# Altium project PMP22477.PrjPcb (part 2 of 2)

## Sheet PMP22477_RevC_SH3.SchDoc: Power Limit Circuit
size 431 x 279 mm; Date: Not shown in title block; ApprovedBy: Not shown in title block; CheckedBy: Not shown in title block; Author: Not shown in title block; CompanyName: Not shown in title block; DrawnBy: D Strasser; Engineer: Not shown in title block; Organization: Not shown in title block; Address1: Not shown in title block; Address2: Not shown in title block; Address3: Not shown in title block; Address4: Not shown in title block; DocumentNumber: 3; Revision: Use project parameter SCH_Rev; SheetNumber: 3; SheetTotal: 3; PageSetup: Record=PageOptions¦CenterHorizontal=True¦CenterVertical=True¦PrintScale=1.00¦XCorrection=1.00¦YCorrection=1.00¦PrintKind=0¦BorderSize=5000000¦LeftOffset=0¦BottomOffset=0¦Orientation=2¦PaperLength=1000¦PaperWidth=1000¦Scale=100¦PaperSource=15¦PrintQuality=600¦MediaType=1¦DitherType=10¦PaperKind=Letter¦PrintScaleMode=1
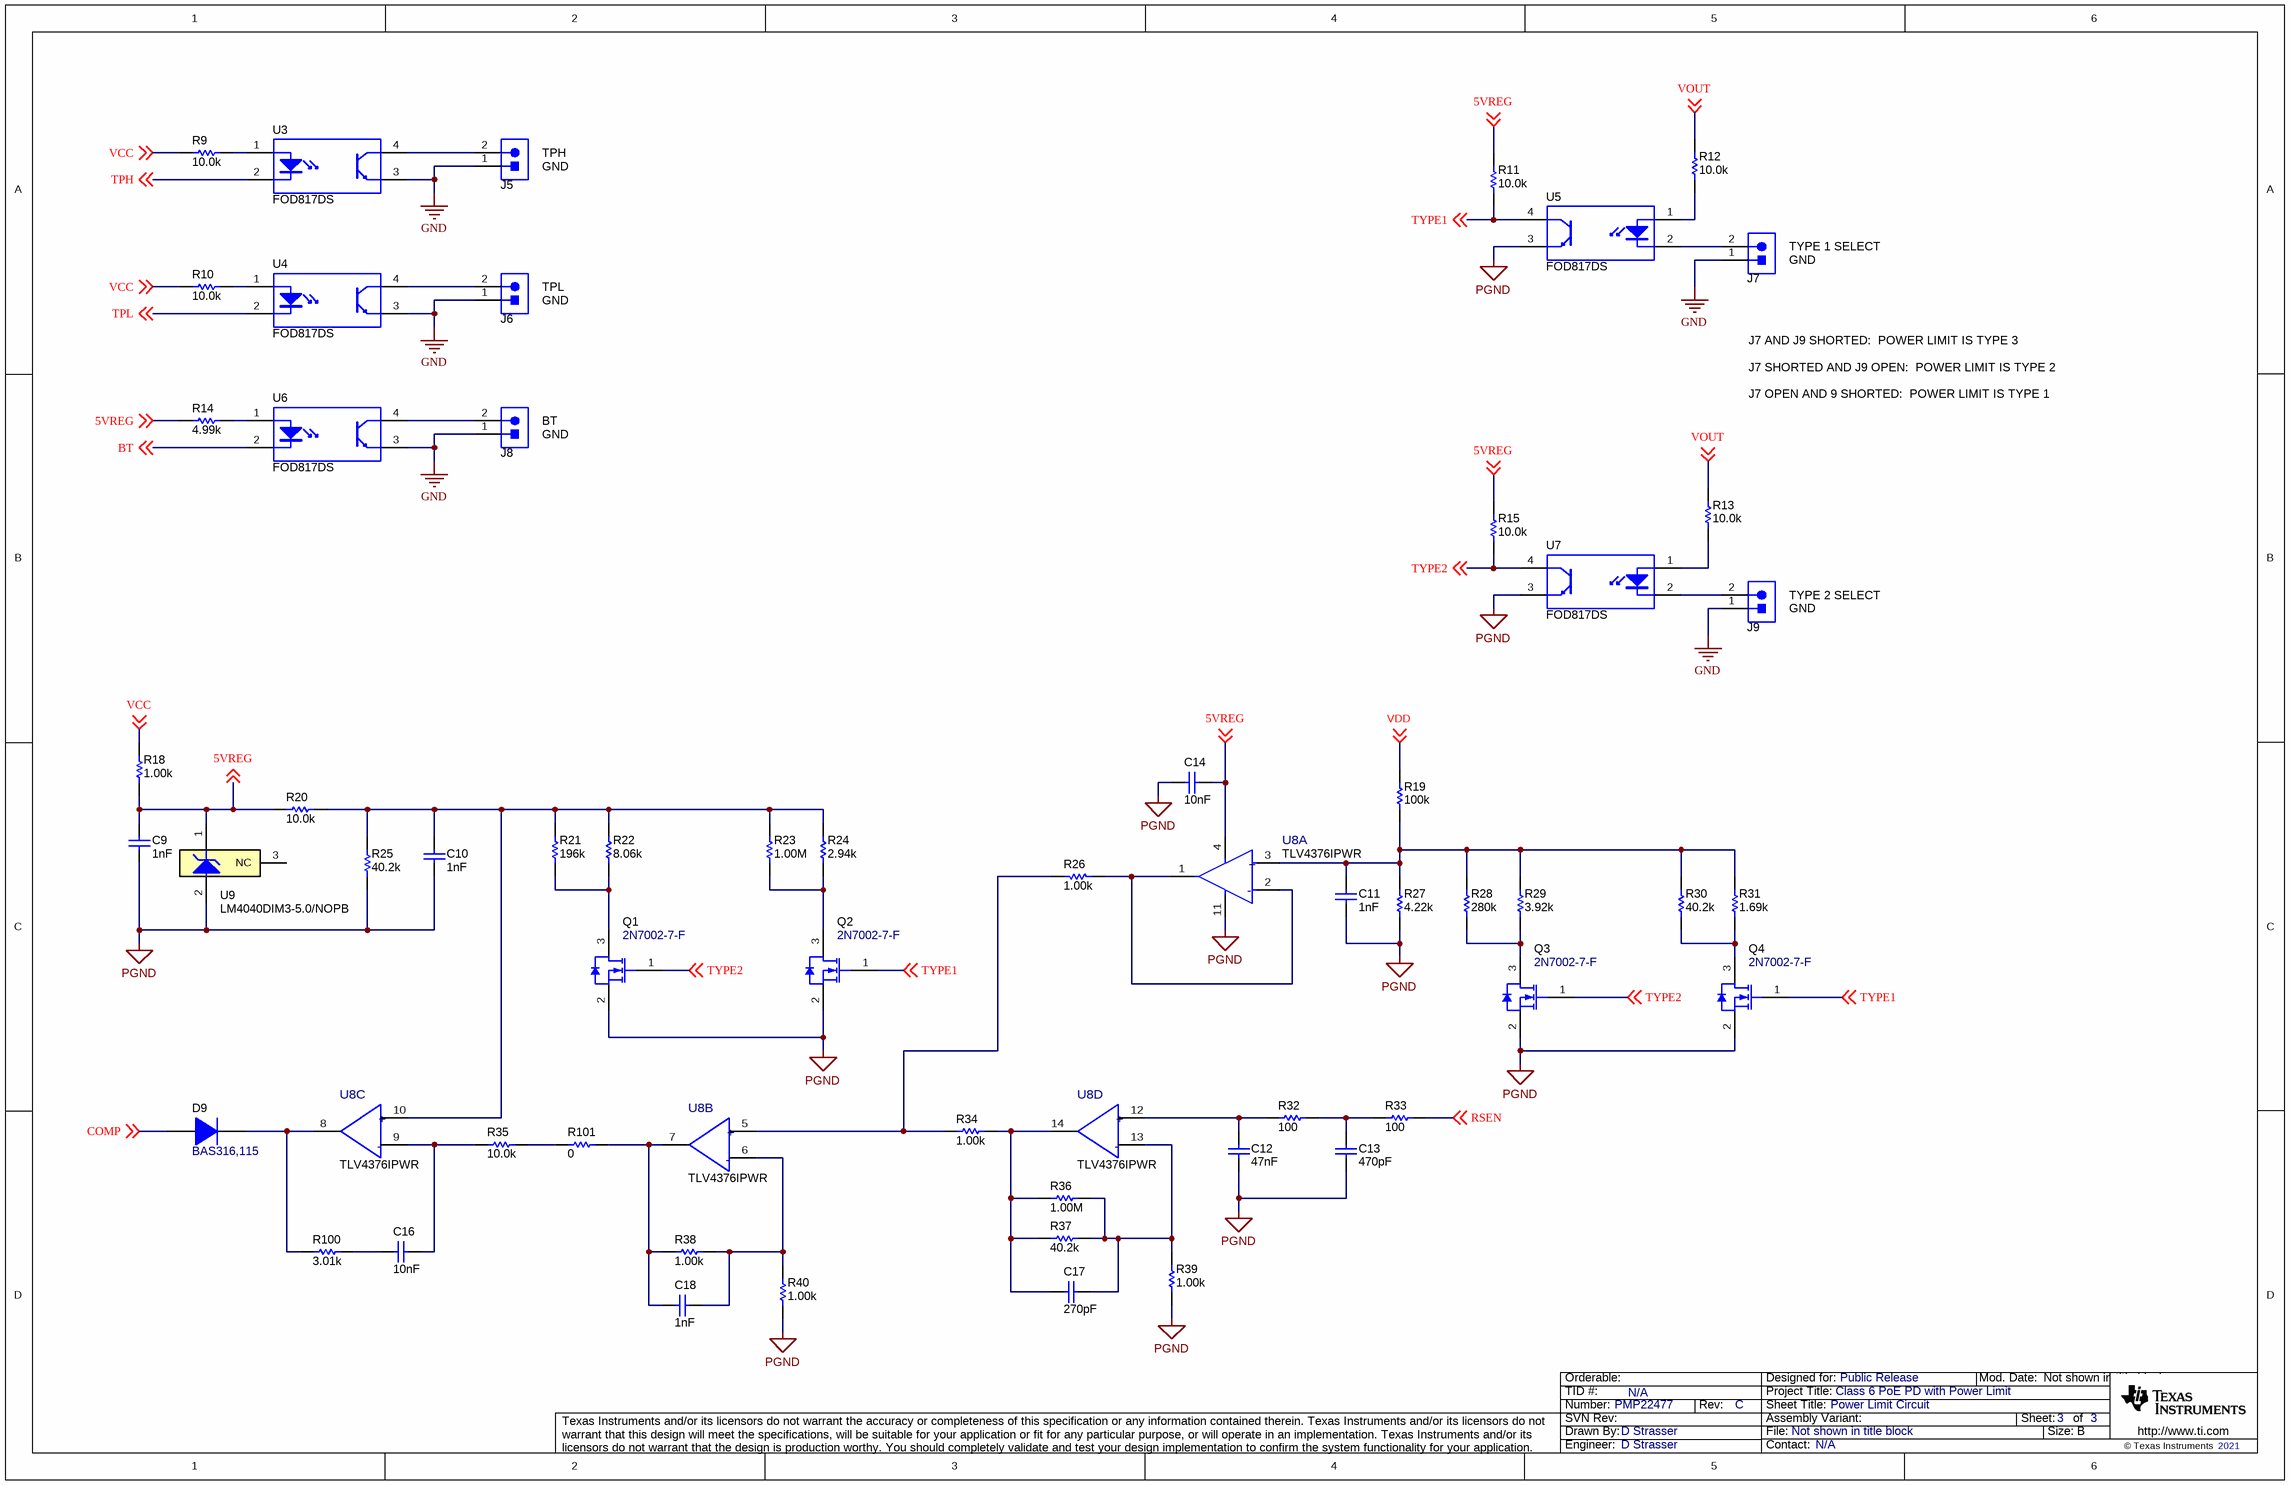
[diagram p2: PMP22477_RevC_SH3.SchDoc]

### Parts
C9  Cap_F: 1nF  [0603L]  (hidden comment: 885012206083)
C10  Cap_F: 1nF  [0603L]  (hidden comment: 885012206083)
C11  Cap_F: 1nF  [0603L]  (hidden comment: 885012206083)
C12  Cap_F: 47nF  [0603L]  (hidden comment: GRM188R71C473KA01D)
C13  ValueDisplayed: 470pF  [0603L]  (hidden comment: GRM1885C1H471JA01D)
C14  Cap_F: 10nF  [0603L]  (hidden comment: GRM188R71H103KA01D)
C16  Cap_F: 10nF  [0603L]  (hidden comment: GRM188R71H103KA01D)
C17  ValueDisplayed: 270pF  [0603L]  (hidden comment: GRM1885C1H271JA01D)
C18  Cap_F: 1nF  [0603L]  (hidden comment: 885012206083)
D9  BAS316,115  [SOD-323]
J5  TSW-102-07-G-S  [TSW-102-07-G-S]  (value not drawn)
J6  TSW-102-07-G-S  [TSW-102-07-G-S]  (value not drawn)
J7  TSW-102-07-G-S  [TSW-102-07-G-S]  (value not drawn)
J8  TSW-102-07-G-S  [TSW-102-07-G-S]  (value not drawn)
J9  TSW-102-07-G-S  [TSW-102-07-G-S]  (value not drawn)
Q1  2N7002-7-F  [SOT-23L]
Q2  2N7002-7-F  [SOT-23L]
Q3  2N7002-7-F  [SOT-23L]
Q4  2N7002-7-F  [SOT-23L]
R9  ValueDisplayed: 10.0k  [0603L]  (hidden comment: CRCW060310K0FKEA)
R10  ValueDisplayed: 10.0k  [0603L]  (hidden comment: CRCW060310K0FKEA)
R11  ValueDisplayed: 10.0k  [0603L]  (hidden comment: CRCW060310K0FKEA)
R12  ValueDisplayed: 10.0k  [0603L]  (hidden comment: CRCW060310K0FKEA)
R13  ValueDisplayed: 10.0k  [0603L]  (hidden comment: CRCW060310K0FKEA)
R14  ValueDisplayed: 4.99k  [0603L]  (hidden comment: CRCW06034K99FKEA)
R15  ValueDisplayed: 10.0k  [0603L]  (hidden comment: CRCW060310K0FKEA)
R18  ValueDisplayed: 1.00k  [0603L]  (hidden comment: CRCW06031K00FKEA)
R19  ValueDisplayed: 100k  [0603L]  (hidden comment: CRCW0603100KFKEA)
R20  ValueDisplayed: 10.0k  [0603L]  (hidden comment: CRCW060310K0FKEA)
R21  ValueDisplayed: 196k  [0603L]  (hidden comment: CRCW0603196KFKEA)
R22  ValueDisplayed: 8.06k  [0603L]  (hidden comment: CRCW06038K06FKEA)
R23  ValueDisplayed: 1.00M  [0603L]  (hidden comment: CRCW06031M00FKEA)
R24  ValueDisplayed: 2.94k  [0603L]  (hidden comment: CRCW06032K94FKEA)
R25  ValueDisplayed: 40.2k  [0603L]  (hidden comment: CRCW060340K2FKEA)
R26  ValueDisplayed: 1.00k  [0603L]  (hidden comment: CRCW06031K00FKEA)
R27  ValueDisplayed: 4.22k  [0603L]  (hidden comment: CRCW06034K22FKEA)
R28  ValueDisplayed: 280k  [0603L]  (hidden comment: CRCW0603280KFKEA)
R29  ValueDisplayed: 3.92k  [0603L]  (hidden comment: CRCW06033K92FKEA)
R30  ValueDisplayed: 40.2k  [0603L]  (hidden comment: CRCW060340K2FKEA)
R31  ValueDisplayed: 1.69k  [0603L]  (hidden comment: CRCW06031K69FKEA)
R32  ValueDisplayed: 100  [0603L]  (hidden comment: CRCW0603100RFKEA)
R33  ValueDisplayed: 100  [0603L]  (hidden comment: CRCW0603100RFKEA)
R34  ValueDisplayed: 1.00k  [0603L]  (hidden comment: CRCW06031K00FKEA)
R35  ValueDisplayed: 10.0k  [0603L]  (hidden comment: CRCW060310K0FKEA)
R36  ValueDisplayed: 1.00M  [0603L]  (hidden comment: CRCW06031M00FKEA)
R37  ValueDisplayed: 40.2k  [0603L]  (hidden comment: CRCW060340K2FKEA)
R38  ValueDisplayed: 1.00k  [0603L]  (hidden comment: CRCW06031K00FKEA)
R39  ValueDisplayed: 1.00k  [0603L]  (hidden comment: CRCW06031K00FKEA)
R40  ValueDisplayed: 1.00k  [0603L]  (hidden comment: CRCW06031K00FKEA)
R100  ValueDisplayed: 3.01k  [0603L]  (hidden comment: CRCW06033K01FKEA)
R101  ValueDisplayed: 0  [0603L]  (hidden comment: ERJ-3GEY0R00V)
U3  FOD817DS  [N04C]
U4  FOD817DS  [N04C]
U5  FOD817DS  [N04C]
U6  FOD817DS  [N04C]
U7  FOD817DS  [N04C]
U8  TLV4376IPWR  [PW0014A-MFG]  (parts A,B,C,D of 4)
U9  LM4040DIM3-5.0/NOPB  [DBZ0003A_L]

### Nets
GND: J5.1 J6.1 J7.1 J8.1 J9.1 U3.3(E) U4.3(E) U6.3(E)
PGND: C9.1 C10.1 C11.1 C12.1 C13.1 C14.1 Q1.2(S) Q2.2(S) Q3.2(S) Q4.2(S) R25.2 R27.1 R39.2 R40.1 U5.3(E) U7.3(E) U8.11(V-) U9.2(A)
5VREG: C9.2 C14.2 R11.1 R14.1 R15.1 R18.1 R20.2 U8.4(V+) U9.1(K) ; off-sheet 5VREG
BT: U6.2(K) ; off-sheet BT
COMP: D9.2(A) ; off-sheet COMP
RSEN: R33.2 ; off-sheet RSEN
TPH: U3.2(K) ; off-sheet TPH
TPL: U4.2(K) ; off-sheet TPL
TYPE1: Q2.1(G) Q4.1(G) R11.2 U5.4(C) ; off-sheet TYPE1
TYPE2: Q1.1(G) Q3.1(G) R15.2 U7.4(C) ; off-sheet TYPE2
VCC: R9.2 R10.2 R18.2 ; off-sheet VCC
VDD: R19.2 ; off-sheet VDD
VOUT: R12.1 R13.1 ; off-sheet VOUT
NetC10_2: C10.2 R20.1 R21.1 R22.1 R23.2 R24.1 R25.1 U8.10(+IN_C)
NetC11_2: C11.2 R19.1 R27.2 R28.1 R29.1 R30.1 R31.1 U8.3(+IN_A)
NetC12_2: C12.2 R32.1 U8.12(+IN_D)
NetC13_2: C13.2 R32.2 R33.1
NetC16_1: C16.1 R100.2
NetC16_2: C16.2 R35.1 U8.9(-IN_C)
NetC17_1: C17.1 R36.1 R37.2 R39.1 U8.13(-IN_D)
NetC17_2: C17.2 R34.2 R36.2 R37.1 U8.14(OUT_D)
NetC18_1: C18.1 R38.2 R40.2 U8.6(-IN_B)
NetC18_2: C18.2 R38.1 R101.1 U8.7(OUT_B)
NetD9_1: D9.1(K) R100.1 U8.8(OUT_C)
NetJ5_2: J5.2 U3.4(C)
NetJ6_2: J6.2 U4.4(C)
NetJ7_2: J7.2 U5.2(K)
NetJ8_2: J8.2 U6.4(C)
NetJ9_2: J9.2 U7.2(K)
NetQ1_3: Q1.3(D) R21.2 R22.2
NetQ2_3: Q2.3(D) R23.1 R24.2
NetQ3_3: Q3.3(D) R28.2 R29.2
NetQ4_3: Q4.3(D) R30.2 R31.2
NetR9_1: R9.1 U3.1(A)
NetR10_1: R10.1 U4.1(A)
NetR12_2: R12.2 U5.1(A)
NetR13_2: R13.2 U7.1(A)
NetR14_2: R14.2 U6.1(A)
NetR26_1: R26.1 U8.1(OUT_A) U8.2(-IN_A)
NetR26_2: R26.2 R34.1 U8.5(+IN_B)
NetR35_2: R35.2 R101.2

Not connected (* = marked no-connect by the designer): U9 3(NC)

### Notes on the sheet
- (near J5) GND
- (near J5) TPH
- (near J6) GND
- (near J6) TPL
- (near J7) TYPE 1 SELECT
- (near J7) GND
- J7 AND J9 SHORTED:  POWER LIMIT IS TYPE 3
- J7 SHORTED AND J9 OPEN:  POWER LIMIT IS TYPE 2
- (near J8) GND
- (near J8) BT
- J7 OPEN AND 9 SHORTED:  POWER LIMIT IS TYPE 1
- (near J9) GND
- (near J9) TYPE 2 SELECT

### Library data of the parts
C9-C11 C18 = CMP-0064933-4: CAP, CERM, 1000 pF, 50 V,+/- 10%, X7R, 0603; Manufacturer: Wurth Elektronik; TaMin_C: -55°C; Polarized: N; SizeAreaWB_mm2: 4.68; Value1: Unknown; U/M: EA; Value: 1000pF; TaMax_C: 125°C; SizeZ_mm: 1; SizeX_mm: 1.6; SizeY_mm: 0.8; Cap_Case: 0603; Value2: 50V; SizeArea_mm2: 1.28; AEC Category: Q200
C12 = CMP-0007397-4: CAP, CERM, 0.047 uF, 16 V, +/- 10%, X7R, 0603; Manufacturer: MuRata; TaMin_C: -55°C; Polarized: N; SizeAreaWB_mm2: 4.68; Value1: Unknown; U/M: EA; TaMax_C: 125°C; SizeZ_mm: 1; SizeX_mm: 1.6; SizeY_mm: 0.8; Cap_Case: 0603; Value2: 16V; SizeArea_mm2: 1.28; AEC Category: Q200
C13 = CMP-0007221-4: CAP, CERM, 470 pF, 50 V, +/- 5%, C0G/NP0, 0603; Manufacturer: MuRata; TaMin_C: -55°C; Polarized: N; SizeAreaWB_mm2: 4.68; Value1: Unknown; U/M: EA; Value: 470pF; TaMax_C: 125°C; SizeZ_mm: 1; SizeX_mm: 1.6; SizeY_mm: 0.8; Cap_Case: 0603; Value2: 50V; SizeArea_mm2: 1.28; AEC Category: Q200
C14 C16 = CMP-0007433-4: CAP, CERM, 0.01 uF, 50 V, +/- 10%, X7R, 0603; Manufacturer: MuRata; TaMin_C: -55°C; Polarized: N; SizeAreaWB_mm2: 4.68; Value1: Unknown; U/M: EA; Value: 0.01uF; TaMax_C: 125°C; SizeZ_mm: 1; SizeX_mm: 1.6; SizeY_mm: 0.8; Cap_Case: 0603; Value2: 50V; SizeArea_mm2: 1.28; AEC Category: Q200
C17 = CMP-0007203-4: CAP, CERM, 270 pF, 50 V, +/- 5%, C0G/NP0, 0603; Manufacturer: MuRata; TaMin_C: -55°C; Polarized: N; SizeAreaWB_mm2: 4.68; Value1: Unknown; U/M: EA; Value: 270pF; TaMax_C: 125°C; SizeZ_mm: 1; SizeX_mm: 1.6; SizeY_mm: 0.8; Cap_Case: 0603; Value2: 50V; SizeArea_mm2: 1.28; AEC Category: Q200
D9 = CMP-0029006-2: Diode, Ultrafast, 100 V, 0.25 A, SOD-323; Manufacturer: Nexperia; SizeY_mm: 1.35; Value1: 0.25A; SizeAreaWB_mm2: 8.695; SizeZ_mm: 1; Io_A: 250mA; Value2: 1.4V; SizeX_mm: 2.7; Green_REACh: Incomplete; TJmax_C: 150°C; Green_Lifecycle: Not Set; Vr_V: 100V; AEC Category: Q101; Value: 100V; SizeArea_mm2: 3.645
J5-J9 = CMP-0075405-3: Header, 100mil, 2x1, Gold, TH; Manufacturer: Samtec; Current_A: 6.3A; Green_Lifecycle: Active; Pitch_mm: 2.54; Cert_CSA: Y; Cert_VDE: N; Green_REACh: Passed; Row_Count: 1; Gender: Male; Voltage_V: 550V
Q1-Q4 = CMP-0000769-1: MOSFET, N-CH, 60 V, 0.17 A, SOT-23; Alternate Manufacturer: None; Manufacturer: Diodes Inc.; SizeZ_mm: 1.1; ChType: N; Value2: 223 nC; Value1: 7; VdsMax_V: 60V; SizeX_mm: 2.5; SizeY_mm: 3; Vgs_V: 20V; Value: 60V; Rdson45_ohm: 7.5; AEC Category: Q101; IdsMax_A: 170mA; SizeAreaWB_mm2: 14; U/M: EA; QgTyp_nC: 223
R9-R13 R15 = CMP-0021998-4: RES, 10.0 k, 1%, 0.1 W, AEC-Q200 Grade 0, 0603; Manufacturer: Vishay-Dale; CompType: Resistor; Value: 10.0k; Res_ohm: 10k; Value_Code: 10k0; Power_W: 100mW; Value2: 0.1W; VDC_V: 75V; TempCo: 100 ppm/C; SizeArea_mm2: 1.28; SizeX_mm: 1.6; SizeY_mm: 0.8; SizeZ_mm: 1; EIA_Code: E96; AEC Category: Q200; AEC Qualified: Y; AEC Grade: 0
R14 = CMP-0022458-4: RES, 4.99 k, 1%, 0.1 W, AEC-Q200 Grade 0, 0603; Manufacturer: Vishay-Dale; Power_W: 100mW; TempCo: 100 ppm/C; Value_Code: 4k99; Value: 4.99k; EIA_Code: E96; SizeX_mm: 1.6; SizeY_mm: 0.8; SizeZ_mm: 1; Value2: 0.1W; SizeArea_mm2: 1.28; AEC Qualified: Y; VDC_V: 75V; AEC Category: Q200; AEC Grade: 0
R18 R26 R34 R38-R40 = CMP-0022109-5: RES, 1.00 k, 1%, 0.1 W, AEC-Q200 Grade 0, 0603; Manufacturer: Vishay-Dale; Power_W: 100mW; TempCo: 100 ppm/C; Value_Code: 1k00; Value: 1.00k; EIA_Code: E96; Res_ohm: 1k; SizeX_mm: 1.6; SizeY_mm: 0.8; SizeZ_mm: 1; Value2: 0.1W; SizeArea_mm2: 1.28; AEC Qualified: Y; VDC_V: 75V; AEC Category: Q200; AEC Grade: 0
R19 = CMP-0021990-4: RES, 100 k, 1%, 0.1 W, AEC-Q200 Grade 0, 0603; Manufacturer: Vishay-Dale; Power_W: 100mW; TempCo: 100 ppm/C; Value: 100k; EIA_Code: E96; SizeX_mm: 1.6; SizeY_mm: 0.8; SizeZ_mm: 1; Value2: 0.1W; SizeArea_mm2: 1.28; AEC Qualified: Y; VDC_V: 75V; AEC Category: Q200; AEC Grade: 0
R20 R35 = CMP-0021998-4: RES, 10.0 k, 1%, 0.1 W, AEC-Q200 Grade 0, 0603; Manufacturer: Vishay-Dale; Power_W: 100mW; TempCo: 100 ppm/C; Value_Code: 10k0; Value: 10.0k; EIA_Code: E96; Res_ohm: 10k; SizeX_mm: 1.6; SizeY_mm: 0.8; SizeZ_mm: 1; Value2: 0.1W; SizeArea_mm2: 1.28; AEC Qualified: Y; VDC_V: 75V; AEC Category: Q200; AEC Grade: 0
R21 = CMP-0022103-4: RES, 196 k, 1%, 0.1 W, AEC-Q200 Grade 0, 0603; Manufacturer: Vishay-Dale; Power_W: 100mW; TempCo: 100 ppm/C; Value: 196k; EIA_Code: E96; SizeX_mm: 1.6; SizeY_mm: 0.8; SizeZ_mm: 1; Value2: 0.1W; SizeArea_mm2: 1.28; AEC Qualified: Y; VDC_V: 75V; AEC Category: Q200; AEC Grade: 0
R22 = CMP-0022634-4: RES, 8.06 k, 1%, 0.1 W, AEC-Q200 Grade 0, 0603; Manufacturer: Vishay-Dale; Power_W: 100mW; TempCo: 100 ppm/C; Value_Code: 8k06; Value: 8.06k; EIA_Code: E96; SizeX_mm: 1.6; SizeY_mm: 0.8; SizeZ_mm: 1; Value2: 0.1W; SizeArea_mm2: 1.28; AEC Qualified: Y; VDC_V: 75V; AEC Category: Q200; AEC Grade: 0
R23 R36 = CMP-0022138-4: RES, 1.00 M, 1%, 0.1 W, AEC-Q200 Grade 0, 0603; Manufacturer: Vishay-Dale; Power_W: 100mW; TempCo: 100 ppm/C; Value_Code: 1M00; Value: 1.00Meg; EIA_Code: E96; Res_ohm: 1M; SizeX_mm: 1.6; SizeY_mm: 0.8; SizeZ_mm: 1; Value2: 0.1W; SizeArea_mm2: 1.28; AEC Qualified: Y; VDC_V: 75V; AEC Category: Q200; AEC Grade: 0
R24 = CMP-0022284-4: RES, 2.94 k, 1%, 0.1 W, AEC-Q200 Grade 0, 0603; Manufacturer: Vishay-Dale; Power_W: 100mW; TempCo: 100 ppm/C; Value_Code: 2k94; Value: 2.94k; EIA_Code: E96; SizeX_mm: 1.6; SizeY_mm: 0.8; SizeZ_mm: 1; Value2: 0.1W; SizeArea_mm2: 1.28; AEC Qualified: Y; VDC_V: 75V; AEC Category: Q200; AEC Grade: 0
R25 R30 R37 = CMP-0022410-4: RES, 40.2 k, 1%, 0.1 W, AEC-Q200 Grade 0, 0603; Manufacturer: Vishay-Dale; Power_W: 100mW; TempCo: 100 ppm/C; Value_Code: 40k2; Value: 40.2k; EIA_Code: E96; SizeX_mm: 1.6; SizeY_mm: 0.8; SizeZ_mm: 1; Value2: 0.1W; SizeArea_mm2: 1.28; AEC Qualified: Y; VDC_V: 75V; AEC Category: Q200; AEC Grade: 0
R27 = CMP-0022451-4: RES, 4.22 k, 1%, 0.1 W, AEC-Q200 Grade 0, 0603; Manufacturer: Vishay-Dale; Power_W: 100mW; TempCo: 100 ppm/C; Value_Code: 4k22; Value: 4.22k; EIA_Code: E96; SizeX_mm: 1.6; SizeY_mm: 0.8; SizeZ_mm: 1; Value2: 0.1W; SizeArea_mm2: 1.28; AEC Qualified: Y; VDC_V: 75V; AEC Category: Q200; AEC Grade: 0
R28 = CMP-0022256-4: RES, 280 k, 1%, 0.1 W, AEC-Q200 Grade 0, 0603; Manufacturer: Vishay-Dale; Power_W: 100mW; TempCo: 100 ppm/C; Value: 280k; EIA_Code: E96; SizeX_mm: 1.6; SizeY_mm: 0.8; SizeZ_mm: 1; Value2: 0.1W; SizeArea_mm2: 1.28; AEC Qualified: Y; VDC_V: 75V; AEC Category: Q200; AEC Grade: 0
R29 = CMP-0022383-4: RES, 3.92 k, 1%, 0.1 W, AEC-Q200 Grade 0, 0603; Manufacturer: Vishay-Dale; Power_W: 100mW; TempCo: 100 ppm/C; Value_Code: 3k92; Value: 3.92k; EIA_Code: E96; SizeX_mm: 1.6; SizeY_mm: 0.8; SizeZ_mm: 1; Value2: 0.1W; SizeArea_mm2: 1.28; AEC Qualified: Y; VDC_V: 75V; AEC Category: Q200; AEC Grade: 0
R31 = CMP-0022131-4: RES, 1.69 k, 1%, 0.1 W, AEC-Q200 Grade 0, 0603; Manufacturer: Vishay-Dale; Power_W: 100mW; TempCo: 100 ppm/C; Value_Code: 1k69; Value: 1.69k; EIA_Code: E96; SizeX_mm: 1.6; SizeY_mm: 0.8; SizeZ_mm: 1; Value2: 0.1W; SizeArea_mm2: 1.28; AEC Qualified: Y; VDC_V: 75V; AEC Category: Q200; AEC Grade: 0
R32 R33 = CMP-0021991-4: RES, 100, 1%, 0.1 W, AEC-Q200 Grade 0, 0603; Manufacturer: Vishay-Dale; Power_W: 100mW; TempCo: 100 ppm/C; Value_Code: 100R; Value: 100; EIA_Code: E96; SizeX_mm: 1.6; SizeY_mm: 0.8; SizeZ_mm: 1; Value2: 0.1W; SizeArea_mm2: 1.28; AEC Qualified: Y; VDC_V: 75V; AEC Category: Q200; AEC Grade: 0
R100 = CMP-0022371-4: RES, 3.01 k, 1%, 0.1 W, AEC-Q200 Grade 0, 0603; Manufacturer: Vishay-Dale; Power_W: 100mW; TempCo: 100 ppm/C; Value_Code: 3k01; Value: 3.01k; EIA_Code: E96; SizeX_mm: 1.6; SizeY_mm: 0.8; SizeZ_mm: 1; Value2: 0.1W; SizeArea_mm2: 1.28; AEC Qualified: Y; VDC_V: 75V; AEC Category: Q200; AEC Grade: 0
R101 = CMP-0025874-4: RES, 0, 5%, 0.1 W, AEC-Q200 Grade 0, 0603; Manufacturer: Panasonic; Power_W: 100mW; TempCo: 600 ppm/C; Value_Code: 0000; Value: 0; EIA_Code: E24; SizeX_mm: 1.6; SizeY_mm: 0.8; SizeZ_mm: 1; Value2: 0.1W; SizeArea_mm2: 1.28; AEC Qualified: Y; VDC_V: 50V; AEC Category: Q200; SizeAreaWB_mm2: 4.68
U3-U7 = CMP-0006165-3: Optocoupler, 5 kV, 300-600% CTR, SMT; Manufacturer: Fairchild Semiconductor; CTR (Min): 300%; CTR (Max): 600%; Voltage_Isolation_Vrms: 5kV
U8 = CMP-0089537-1: General Purpose Amplifier 4 Circuit Rail-to-Rail 14-TSSOP; Manufacturer: Texas Instruments; Input Bias Current: 0.0000003uA; TJmax_C: +150°C; Min Dual Supply Voltage: 1.1V; Number Of Channels: 4; Voltage Gain: 126dB; TaMax_C: +125°C; Response Time: 2us; AEC Qualified: No; Nominal Supply Current: 815uA; SizeZ_mm: 1.2mm; TaMin_C: -40°C; Min Supply Voltage: 2.2V; Gain Bandwidth: 5.5MHz; Standoff Height: 0.05mm; Max Dual Supply Voltage: 2.75V; Input Offset Voltage: 0.05mV; Max Supply Voltage: 5.5V
U9 = CMP-0079018-1: Precision Micropower Shunt Voltage Reference, DBZ0003A (SOT-23-3); Alternate PartNumber: LM4040DIM3X-5.0/NOPB; Alternate Manufacturer: Texas Instruments; SizeAreaWB_mm2: 14; SizeZ_mm: 1.12; SizeX_mm: 2.5; SizeY_mm: 3; SizeArea_mm2: 7.5; CompType: IC; AEC Qualified: N; AEC Category: Q200

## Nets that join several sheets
GND: PMP22477_RevC_SH2 (18 pins), PMP22477_RevC_SH3 (8 pins)
PGND: PMP22477_RevC_SH2 (34 pins), PMP22477_RevC_SH3 (18 pins)
BT: PMP22477_RevC_SH2 (U10.12), PMP22477_RevC_SH3 (U6.2)
COMP: PMP22477_RevC_SH2 (C41.2 C43.2 U10.35), PMP22477_RevC_SH3 (D9.2)
RSEN: PMP22477_RevC_SH2 (5 pins), PMP22477_RevC_SH3 (R33.2)
TPH: PMP22477_RevC_SH2 (U10.13), PMP22477_RevC_SH3 (U3.2)
TPL: PMP22477_RevC_SH2 (U10.14), PMP22477_RevC_SH3 (U4.2)
VCC: PMP22477_RevC_SH2 (C44.1 D14.1 R57.1 U10.42), PMP22477_RevC_SH3 (R9.2 R10.2 R18.2)
VDD: PMP22477_RevC_SH1 (C8.1 L1.2), PMP22477_RevC_SH2 (9 pins), PMP22477_RevC_SH3 (R19.2)
VOUT: PMP22477_RevC_SH2 (15 pins), PMP22477_RevC_SH3 (R12.1 R13.1)
VSS: PMP22477_RevC_SH1 (C8.2 L3.2), PMP22477_RevC_SH2 (9 pins)

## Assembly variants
001: not fitted C46 C49 D17 D18 J3 J4 J10 J12 Q8 Q9 Q10 Q11 R23 R36 R51 R63 R65 R70 R75 R76 U1 U2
